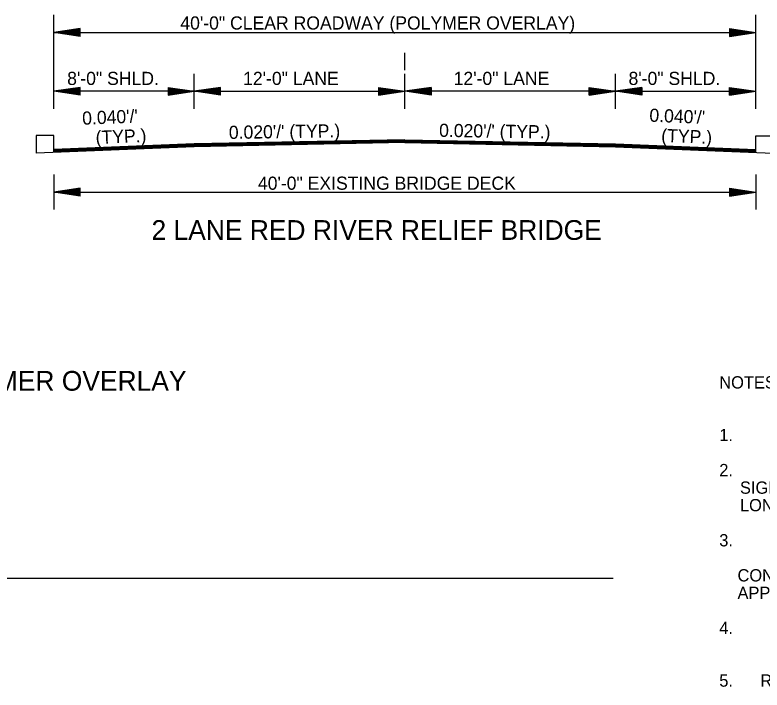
# Model space of a CAD drawing. Extents: x 545241 to 1930787, y -1971772 to 596640.
# Drawn here: x 547405.9 to 547831.8, y -1958323.3 to -1957938.4 of the extents above; entities that cross this region are included whole.
import ezdxf

# ---------------------------------------------------------------- set-up
doc = ezdxf.new("R2010")
doc.units = 0
for name, color, linetype in [('R_Border', 7, 'Continuous'), ('R_Border Notes', 7, 'Continuous'), ('R_Draft', 7, 'Continuous')]:
    doc.layers.add(name, color=color, linetype=linetype)

msp = doc.modelspace()

# ---------------------------------------------------------------- linework, layer by layer
at = {"layer": 'R_Border'}
for p, q in [((547428.13, -1958007.22), (547417.97, -1958007.22)), ((547417.97, -1958007.22), (547417.97, -1958017.23)), ((547428.13, -1958016.83), (547428.13, -1958007.22)), ((547828.13, -1958007.42), (547838.3, -1958007.42)), ((547828.13, -1958016.83), (547828.13, -1958007.42)), ((546718.93, -1958259.48), (547746.88, -1958259.48))]:
    msp.add_line(p, q, dxfattribs=at)
at = {"layer": 'R_Draft'}
for p, q in [((547428.13, -1957991.95), (547428.13, -1957938.41)), ((547828.13, -1957991.95), (547828.13, -1957938.41)), ((547443.13, -1957946.16), (547428.13, -1957948.41)), ((547428.13, -1957948.41), (547828.13, -1957948.41)), ((547443.13, -1957950.66), (547428.13, -1957948.41)), ((547443.13, -1957946.54), (547430.64, -1957948.41)), ((547443.13, -1957950.29), (547430.64, -1957948.41)), ((547443.13, -1957946.92), (547433.22, -1957948.41)), ((547443.13, -1957949.9), (547433.22, -1957948.41)), ((547443.13, -1957947.29), (547435.72, -1957948.41)), ((547443.13, -1957949.53), (547435.72, -1957948.41)), ((547443.13, -1957947.68), (547438.26, -1957948.41)), ((547443.13, -1957949.14), (547438.26, -1957948.41)), ((547443.13, -1957948.06), (547440.76, -1957948.41)), ((547443.13, -1957948.76), (547440.76, -1957948.41)), ((547443.13, -1957950.66), (547443.13, -1957946.16)), ((547813.13, -1957946.16), (547828.13, -1957948.41)), ((547813.13, -1957946.16), (547813.13, -1957950.66)), ((547813.13, -1957946.54), (547825.63, -1957948.41)), ((547813.13, -1957946.92), (547823.05, -1957948.41)), ((547813.13, -1957947.29), (547820.55, -1957948.41)), ((547813.13, -1957947.68), (547818.01, -1957948.41)), ((547813.13, -1957948.06), (547815.5, -1957948.41)), ((547813.13, -1957950.66), (547828.13, -1957948.41)), ((547813.13, -1957949.15), (547818.01, -1957948.41)), ((547813.13, -1957949.9), (547823.05, -1957948.41)), ((547813.13, -1957950.29), (547825.63, -1957948.41)), ((547813.13, -1957949.53), (547820.55, -1957948.41)), ((547813.13, -1957948.76), (547815.5, -1957948.41)), ((547628.13, -1957969.93), (547628.13, -1957960.06)), ((547508.13, -1957991.95), (547508.13, -1957972.06)), ((547628.13, -1957991.95), (547628.13, -1957972.06)), ((547748.13, -1957991.95), (547748.13, -1957972.06)), ((547443.13, -1957979.7), (547428.13, -1957981.95)), ((547508.13, -1957981.95), (547428.13, -1957981.95)), ((547443.13, -1957984.2), (547428.13, -1957981.95)), ((547443.13, -1957980.07), (547430.64, -1957981.95)), ((547443.13, -1957983.82), (547430.64, -1957981.95)), ((547443.13, -1957980.46), (547433.22, -1957981.95)), ((547443.13, -1957983.44), (547433.22, -1957981.95)), ((547443.13, -1957980.83), (547435.72, -1957981.95)), ((547443.13, -1957983.07), (547435.72, -1957981.95)), ((547443.13, -1957981.21), (547438.26, -1957981.95)), ((547443.13, -1957982.68), (547438.26, -1957981.95)), ((547443.13, -1957981.6), (547440.76, -1957981.95)), ((547443.13, -1957982.3), (547440.76, -1957981.95)), ((547443.13, -1957984.2), (547443.13, -1957979.7)), ((547493.13, -1957979.7), (547508.13, -1957981.95)), ((547493.13, -1957979.7), (547493.13, -1957984.2)), ((547493.13, -1957980.07), (547505.63, -1957981.95)), ((547493.13, -1957980.46), (547503.05, -1957981.95)), ((547493.13, -1957980.83), (547500.55, -1957981.95)), ((547493.13, -1957981.22), (547498.01, -1957981.95)), ((547493.13, -1957981.6), (547495.5, -1957981.95)), ((547493.13, -1957984.2), (547508.13, -1957981.95)), ((547493.13, -1957982.68), (547498.01, -1957981.95)), ((547493.13, -1957983.44), (547503.05, -1957981.95)), ((547493.13, -1957983.82), (547505.63, -1957981.95)), ((547493.13, -1957983.07), (547500.55, -1957981.95)), ((547493.13, -1957982.3), (547495.5, -1957981.95)), ((547523.13, -1957979.7), (547508.13, -1957981.95)), ((547523.13, -1957984.2), (547508.13, -1957981.95)), ((547508.13, -1957981.95), (547628.13, -1957981.95)), ((547523.13, -1957980.07), (547510.64, -1957981.95)), ((547523.13, -1957983.82), (547510.64, -1957981.95)), ((547523.13, -1957980.46), (547513.22, -1957981.95)), ((547523.13, -1957983.44), (547513.22, -1957981.95)), ((547523.13, -1957980.83), (547515.72, -1957981.95)), ((547523.13, -1957983.07), (547515.72, -1957981.95)), ((547523.13, -1957981.21), (547518.26, -1957981.95)), ((547523.13, -1957982.68), (547518.26, -1957981.95)), ((547523.13, -1957981.6), (547520.76, -1957981.95)), ((547523.13, -1957982.3), (547520.76, -1957981.95)), ((547523.13, -1957984.2), (547523.13, -1957979.7)), ((547613.13, -1957979.7), (547628.13, -1957981.95)), ((547613.13, -1957979.7), (547613.13, -1957984.2)), ((547613.13, -1957980.07), (547625.63, -1957981.95)), ((547613.13, -1957980.46), (547623.05, -1957981.95)), ((547613.13, -1957980.83), (547620.55, -1957981.95)), ((547613.13, -1957981.22), (547618.01, -1957981.95)), ((547613.13, -1957981.6), (547615.5, -1957981.95)), ((547613.13, -1957984.2), (547628.13, -1957981.95)), ((547613.13, -1957982.68), (547618.01, -1957981.95)), ((547613.13, -1957983.44), (547623.05, -1957981.95)), ((547613.13, -1957983.82), (547625.63, -1957981.95)), ((547613.13, -1957983.07), (547620.55, -1957981.95)), ((547613.13, -1957982.3), (547615.5, -1957981.95)), ((547643.13, -1957979.7), (547628.13, -1957981.95)), ((547748.13, -1957981.95), (547628.13, -1957981.95)), ((547643.13, -1957984.2), (547628.13, -1957981.95)), ((547643.13, -1957980.07), (547630.64, -1957981.95)), ((547643.13, -1957983.82), (547630.64, -1957981.95)), ((547643.13, -1957980.46), (547633.22, -1957981.95)), ((547643.13, -1957983.44), (547633.22, -1957981.95)), ((547643.13, -1957980.83), (547635.72, -1957981.95)), ((547643.13, -1957983.07), (547635.72, -1957981.95)), ((547643.13, -1957981.22), (547638.26, -1957981.95)), ((547643.13, -1957982.68), (547638.26, -1957981.95)), ((547643.13, -1957981.6), (547640.76, -1957981.95)), ((547643.13, -1957982.3), (547640.76, -1957981.95)), ((547643.13, -1957979.7), (547643.13, -1957984.2)), ((547733.13, -1957979.7), (547748.13, -1957981.95)), ((547733.13, -1957984.2), (547733.13, -1957979.7)), ((547733.13, -1957980.07), (547745.63, -1957981.95)), ((547733.13, -1957980.46), (547743.05, -1957981.95)), ((547733.13, -1957980.83), (547740.55, -1957981.95)), ((547733.13, -1957981.21), (547738.01, -1957981.95)), ((547733.13, -1957981.6), (547735.5, -1957981.95)), ((547733.13, -1957984.2), (547748.13, -1957981.95)), ((547733.13, -1957982.68), (547738.01, -1957981.95)), ((547733.13, -1957983.44), (547743.05, -1957981.95)), ((547733.13, -1957983.82), (547745.63, -1957981.95)), ((547733.13, -1957983.07), (547740.55, -1957981.95)), ((547733.13, -1957982.3), (547735.5, -1957981.95)), ((547763.13, -1957979.7), (547748.13, -1957981.95)), ((547763.13, -1957984.2), (547748.13, -1957981.95)), ((547748.13, -1957981.95), (547828.13, -1957981.95)), ((547763.13, -1957980.07), (547750.64, -1957981.95)), ((547763.13, -1957983.82), (547750.64, -1957981.95)), ((547763.13, -1957980.46), (547753.22, -1957981.95)), ((547763.13, -1957983.44), (547753.22, -1957981.95)), ((547763.13, -1957980.83), (547755.72, -1957981.95)), ((547763.13, -1957983.07), (547755.72, -1957981.95)), ((547763.13, -1957981.22), (547758.26, -1957981.95)), ((547763.13, -1957982.68), (547758.26, -1957981.95)), ((547763.13, -1957981.6), (547760.76, -1957981.95)), ((547763.13, -1957982.3), (547760.76, -1957981.95)), ((547763.13, -1957979.7), (547763.13, -1957984.2)), ((547813.13, -1957979.7), (547828.13, -1957981.95)), ((547813.13, -1957984.2), (547813.13, -1957979.7)), ((547813.13, -1957980.07), (547825.63, -1957981.95)), ((547813.13, -1957980.46), (547823.05, -1957981.95)), ((547813.13, -1957980.83), (547820.55, -1957981.95)), ((547813.13, -1957981.21), (547818.01, -1957981.95)), ((547813.13, -1957981.6), (547815.5, -1957981.95)), ((547813.13, -1957984.2), (547828.13, -1957981.95)), ((547813.13, -1957982.68), (547818.01, -1957981.95)), ((547813.13, -1957983.44), (547823.05, -1957981.95)), ((547813.13, -1957983.82), (547825.63, -1957981.95)), ((547813.13, -1957983.07), (547820.55, -1957981.95)), ((547813.13, -1957982.3), (547815.5, -1957981.95)), ((547508.13, -1958011.96), (547428.13, -1958015.16)), ((547508.13, -1958012.26), (547428.13, -1958015.46)), ((547508.13, -1958012.56), (547428.13, -1958015.76)), ((547508.13, -1958012.86), (547428.13, -1958016.06)), ((547628.13, -1958009.56), (547508.13, -1958011.96)), ((547628.14, -1958009.86), (547508.13, -1958012.26)), ((547628.15, -1958010.16), (547508.13, -1958012.56)), ((547628.15, -1958010.46), (547508.13, -1958012.86)), ((547628.16, -1958010.76), (547508.13, -1958013.16)), ((547628.16, -1958011.06), (547508.13, -1958013.46)), ((547628.17, -1958011.23), (547508.13, -1958013.63)), ((547628.1, -1958011.06), (547748.13, -1958013.46)), ((547628.1, -1958011.23), (547748.13, -1958013.63)), ((547628.11, -1958010.76), (547748.13, -1958013.16)), ((547628.12, -1958010.16), (547748.13, -1958012.56)), ((547628.12, -1958010.46), (547748.13, -1958012.86)), ((547628.13, -1958009.56), (547748.13, -1958011.96)), ((547628.13, -1958009.86), (547748.13, -1958012.26)), ((547748.13, -1958011.96), (547828.13, -1958015.16)), ((547748.13, -1958012.26), (547828.13, -1958015.46)), ((547748.13, -1958012.56), (547828.13, -1958015.76)), ((547748.13, -1958012.86), (547828.13, -1958016.06)), ((547508.13, -1958013.63), (547417.97, -1958017.23)), ((547508.13, -1958013.16), (547428.13, -1958016.36)), ((547508.13, -1958013.46), (547428.13, -1958016.66)), ((547748.13, -1958013.16), (547828.13, -1958016.36)), ((547748.13, -1958013.46), (547828.13, -1958016.66)), ((547748.13, -1958013.63), (547838.3, -1958017.23)), ((547428.13, -1958029.41), (547428.13, -1958049.41)), ((547828.13, -1958029.41), (547828.13, -1958049.41)), ((547443.13, -1958037.16), (547428.13, -1958039.41)), ((547443.13, -1958037.54), (547430.64, -1958039.41)), ((547443.13, -1958037.92), (547433.22, -1958039.41)), ((547443.13, -1958038.3), (547435.72, -1958039.41)), ((547443.13, -1958041.66), (547443.13, -1958037.16)), ((547813.13, -1958037.16), (547828.13, -1958039.41)), ((547813.13, -1958037.16), (547813.13, -1958041.66)), ((547813.13, -1958037.54), (547825.63, -1958039.41)), ((547813.13, -1958037.92), (547823.05, -1958039.41)), ((547813.13, -1958038.3), (547820.55, -1958039.41)), ((547428.13, -1958039.41), (547828.13, -1958039.41)), ((547443.13, -1958041.66), (547428.13, -1958039.41)), ((547443.13, -1958041.29), (547430.64, -1958039.41)), ((547443.13, -1958040.91), (547433.22, -1958039.41)), ((547443.13, -1958040.53), (547435.72, -1958039.41)), ((547443.13, -1958038.68), (547438.26, -1958039.41)), ((547443.13, -1958040.14), (547438.26, -1958039.41)), ((547443.13, -1958039.06), (547440.76, -1958039.41)), ((547443.13, -1958039.77), (547440.76, -1958039.41)), ((547813.13, -1958038.69), (547818.01, -1958039.41)), ((547813.13, -1958039.06), (547815.5, -1958039.41)), ((547813.13, -1958041.66), (547828.13, -1958039.41)), ((547813.13, -1958040.15), (547818.01, -1958039.41)), ((547813.13, -1958040.91), (547823.05, -1958039.41)), ((547813.13, -1958041.29), (547825.63, -1958039.41)), ((547813.13, -1958040.53), (547820.55, -1958039.41)), ((547813.13, -1958039.77), (547815.5, -1958039.41))]:
    msp.add_line(p, q, dxfattribs=at)

# ---------------------------------------------------------------- texts
at = {"layer": 'R_Border Notes'}
for s, p in [('NOTES: ', (547807.36, -1958151.4)), ('1.', (547807.36, -1958181.4)), ('2.', (547807.36, -1958201.4)), ('    SIGNS (48" X 48") WITH BLACK LEGEND ON ORANGE BACKGROUND AT ALL ', (547808.76, -1958211.4)), ('    LONGITUDINAL JOINTS DURING MILLING AND PAVING OPERATIONS.', (547808.76, -1958221.4)), ('3.', (547807.36, -1958241.4)), ('    CONSTRUCTION, 2014 EDITION, SECTION 410.07 UNLESS OTHERWISE', (547807.36, -1958261.4)), ('    APPROVED IF AND WHERE BY THE ENGINEER.', (547807.36, -1958271.4)), ('4.', (547807.36, -1958291.4)), ('5.      REFER TO SPECIAL DETAILS AND QUANTITY SHEETS FOR ROADWAY', (547807.36, -1958321.4))]:
    msp.add_text(s, height=7, dxfattribs=at).set_placement(p)
at = {"layer": 'R_Draft'}
for s, height, p in [('40\'-0" CLEAR ROADWAY (POLYMER OVERLAY)', 7.5, (547500.16, -1957946.74)), ('8\'-0" SHLD.', 7.5, (547435.65, -1957978.34)), ('12\'-0" LANE', 7.5, (547535.95, -1957978.34)), ('12\'-0" LANE', 7.5, (547655.95, -1957978.34)), ('8\'-0" SHLD.', 7.5, (547755.65, -1957978.34)), ('40\'-0" EXISTING BRIDGE DECK', 7.5, (547544.39, -1958038.09)), ('2 LANE RED RIVER RELIEF BRIDGE', 11.25, (547483.74, -1958066.66)), ('40 FT. CLEAR ROADWAY BRIDGE - POLYMER OVERLAY', 11.25, (547099.9, -1958152.65))]:
    msp.add_text(s, height=height, dxfattribs=at).set_placement(p)
for s, rotation, p in [("0.040'/' ", 2.2906, (547444.36, -1958001.04)), ("0.040'/' ", 357.7094, (547767.42, -1957999.26)), ('(TYP.)', 2.2906, (547452.01, -1958011.99)), ("0.020'/' (TYP.)", 0.8719, (547527.86, -1958009.13)), ("0.020'/' (TYP.)", 359.1281, (547647.63, -1958007.91)), ('(TYP.)', 357.7094, (547774.17, -1958010.79))]:
    msp.add_text(s, height=7.5, rotation=rotation, dxfattribs=at).set_placement(p)

doc.saveas('drawing.dxf')
